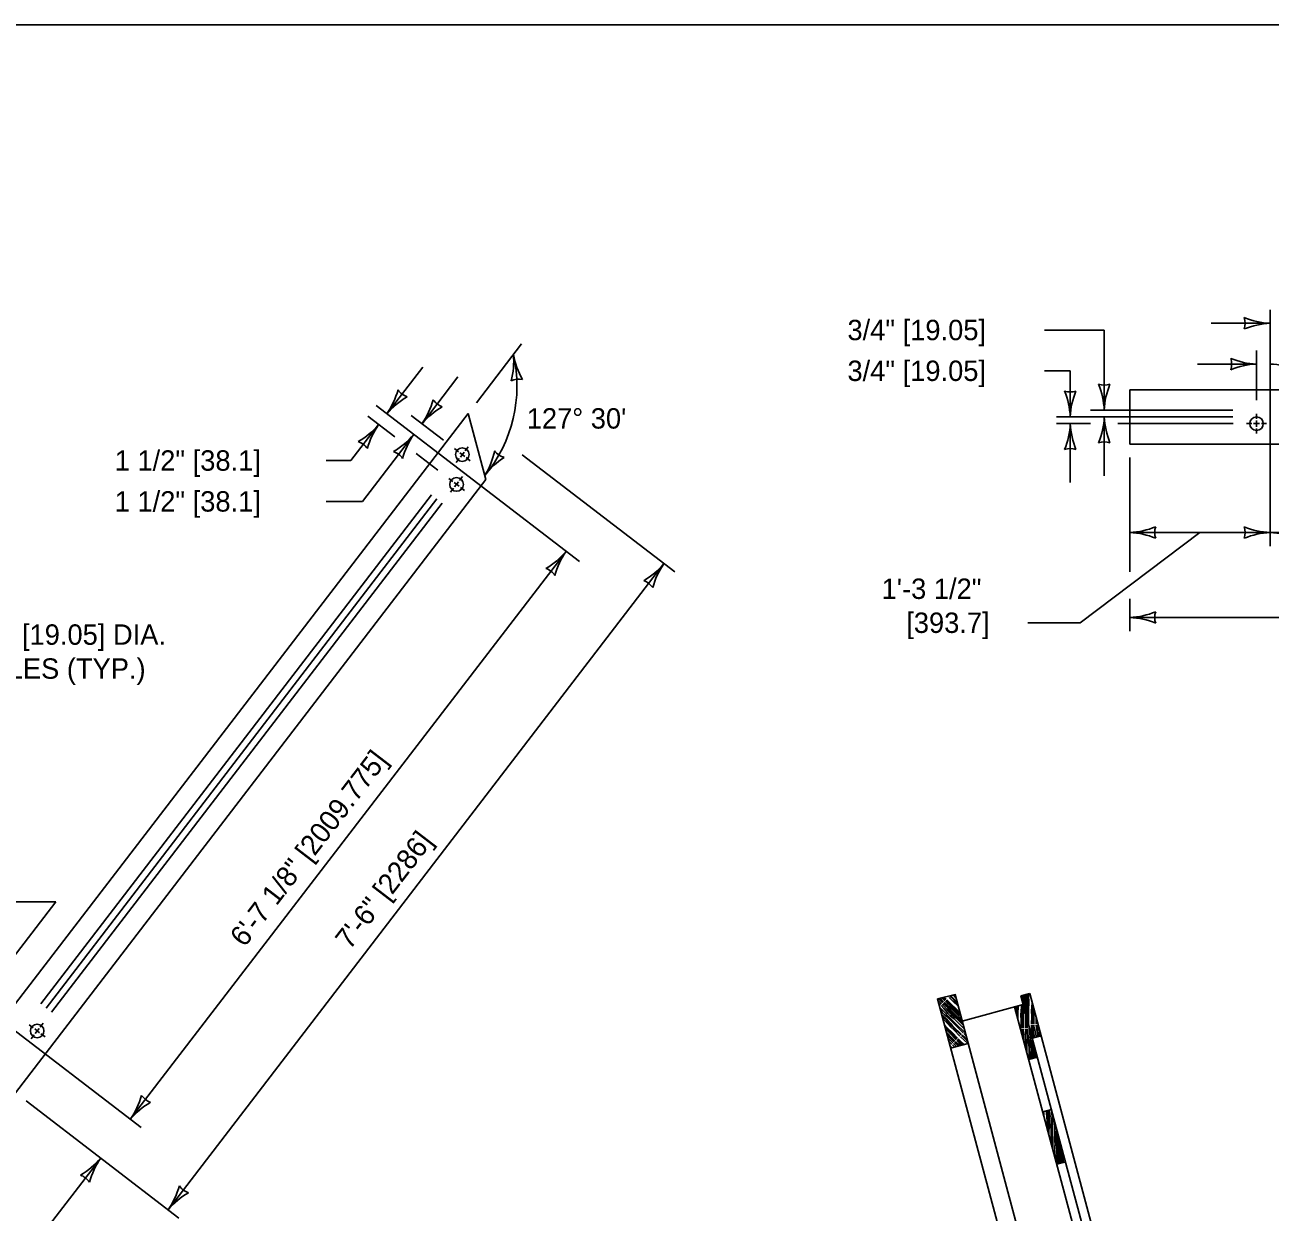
# Model space of a CAD drawing. Extents: x 49991 to 79985, y 47703 to 60542.
# Drawn here: x 50009.323 to 50012.986, y 49995.507 to 49998.999 of the extents above; entities that cross this region are included whole.
import ezdxf

# ---------------------------------------------------------------- set-up
doc = ezdxf.new("R2010")
doc.units = 0
for name, color, linetype in [('Level 1', 7, 'Continuous'), ('Level 2', 7, 'Continuous'), ('Level 3', 7, 'Continuous'), ('Level 4', 7, 'Continuous'), ('Level 5', 7, 'Continuous')]:
    doc.layers.add(name, color=color, linetype=linetype)

msp = doc.modelspace()

# ---------------------------------------------------------------- linework, layer by layer
at = {"layer": 'Level 1'}
for p, q in [((50015.1288, 49997.926), (50012.5733, 49997.926)), ((50012.5733, 49997.926), (50012.5733, 49997.7663)), ((50009.1686, 49995.9554), (50010.6271, 49997.8561)), ((50010.6794, 49997.6615), (50010.6271, 49997.8561)), ((50012.5733, 49997.7663), (50015.1288, 49997.7663)), ((50009.2955, 49995.858), (50010.6794, 49997.6615)), ((50012.0075, 49996.134), (50012.0592, 49996.1469)), ((50012.2427, 49995.2562), (50012.0075, 49996.134)), ((50012.0075, 49996.134), (50012.0076, 49996.1336)), ((50012.7492, 49993.5717), (50012.0592, 49996.1469)), ((50012.0801, 49996.069), (50012.26, 49996.1172)), ((50012.2531, 49996.1429), (50012.2788, 49996.1497)), ((50012.6896, 49994.5138), (50012.2531, 49996.1429)), ((50012.7172, 49994.5138), (50012.2788, 49996.1497)), ((50012.6693, 49994.4868), (50012.2343, 49996.1103)), ((50012.2865, 49996.0181), (50012.3122, 49996.025)), ((50012.0463, 49995.9892), (50012.0978, 49996.0029)), ((50012.2756, 49995.956), (50012.3013, 49995.9629)), ((50012.317, 49995.8017), (50012.3427, 49995.8086)), ((50012.3583, 49995.6475), (50012.384, 49995.6543))]:
    msp.add_line(p, q, dxfattribs=at)
msp.add_lwpolyline([(49999.3835, 49998.9992), (50016.7501, 49998.9992), (50016.7501, 49987.7988), (49999.3835, 49987.7988)], close=True, dxfattribs=at)
for points in [[(50012.0084, 49996.1308), (50012.0194, 49996.1194)], [(50012.0102, 49996.1347), (50012.0226, 49996.1225)], [(50012.0108, 49996.1215), (50012.0163, 49996.1162)], [(50012.0126, 49996.1353), (50012.0241, 49996.1241)], [(50012.0153, 49996.136), (50012.0257, 49996.1256)], [(50012.0207, 49996.1373), (50012.0289, 49996.1288)], [(50012.0213, 49996.1175), (50012.0345, 49996.1052), (50012.0444, 49996.092), (50012.0522, 49996.0841), (50012.0567, 49996.0814), (50012.0629, 49996.0769), (50012.073, 49996.0665), (50012.0837, 49996.0554)], [(50012.0236, 49996.138), (50012.0304, 49996.1304)], [(50012.0245, 49996.1207), (50012.0377, 49996.1084), (50012.05, 49996.0924), (50012.0646, 49996.0796), (50012.0789, 49996.0659), (50012.0816, 49996.0633)], [(50012.026, 49996.1222), (50012.0392, 49996.1099), (50012.0542, 49996.0933), (50012.0661, 49996.0811), (50012.0804, 49996.0674), (50012.0805, 49996.0674)], [(50012.0276, 49996.1237), (50012.0362, 49996.1161), (50012.045, 49996.1083), (50012.0611, 49996.0921), (50012.0779, 49996.0741), (50012.079, 49996.0729)], [(50012.0277, 49996.1391), (50012.0334, 49996.1333)], [(50012.0307, 49996.1269), (50012.0616, 49996.0972), (50012.0766, 49996.0819)], [(50012.0323, 49996.1285), (50012.0394, 49996.1229), (50012.0489, 49996.1143), (50012.075, 49996.0878)], [(50012.0353, 49996.1314), (50012.0482, 49996.1189), (50012.0629, 49996.1045), (50012.0735, 49996.0934)], [(50012.0381, 49996.1416), (50012.0398, 49996.1398)], [(50012.0417, 49996.1379), (50012.0523, 49996.1273), (50012.0683, 49996.1129)], [(50012.0666, 49996.1192), (50012.0647, 49996.1208), (50012.0554, 49996.1311), (50012.0432, 49996.1427)], [(50012.0652, 49996.1243), (50012.0639, 49996.1254), (50012.055, 49996.1353), (50012.0465, 49996.1427)], [(50012.0621, 49996.1361), (50012.057, 49996.1426), (50012.0536, 49996.1455)], [(50012.0596, 49996.1455), (50012.0583, 49996.1467)], [(50012.2551, 49996.1353), (50012.2563, 49996.1436), (50012.2563, 49996.1438)], [(50012.2576, 49996.0478), (50012.257, 49996.0746), (50012.2568, 49996.0937), (50012.2584, 49996.1072), (50012.2576, 49996.1166)], [(50012.2583, 49996.1236), (50012.2608, 49996.1436), (50012.2608, 49996.1449)], [(50012.2617, 49996.1107), (50012.2618, 49996.1213), (50012.263, 49996.1436), (50012.2629, 49996.1455)], [(50012.2652, 49996.0975), (50012.2659, 49996.1155), (50012.2659, 49996.1383), (50012.2654, 49996.1462)], [(50012.2694, 49996.0819), (50012.2695, 49996.0877), (50012.2698, 49996.1188), (50012.2692, 49996.1472)], [(50012.272, 49996.0722), (50012.2725, 49996.0807), (50012.2729, 49996.1398), (50012.2725, 49996.1481)], [(50012.2754, 49996.0596), (50012.2757, 49996.0824), (50012.2754, 49996.1025), (50012.2759, 49996.123), (50012.2757, 49996.1436), (50012.2756, 49996.1489)], [(50012.2845, 49996.0594), (50012.2851, 49996.0829), (50012.2845, 49996.0982), (50012.2857, 49996.1225), (50012.2856, 49996.1243)], [(50012.0897, 49996.0336), (50012.0588, 49996.0633), (50012.0377, 49996.0847), (50012.0304, 49996.0933), (50012.0142, 49996.1089)], [(50012.0161, 49996.1018), (50012.0162, 49996.1018), (50012.0228, 49996.0932), (50012.0271, 49996.0886), (50012.0361, 49996.0812), (50012.0503, 49996.0661), (50012.0827, 49996.0343)], [(50012.0181, 49996.1143), (50012.0266, 49996.1055), (50012.0336, 49996.0975), (50012.0381, 49996.0911), (50012.0447, 49996.0842), (50012.0497, 49996.0804), (50012.0562, 49996.0752), (50012.0638, 49996.0682), (50012.0862, 49996.0462)], [(50012.078, 49996.0296), (50012.0518, 49996.0552), (50012.049, 49996.0587), (50012.0482, 49996.0611), (50012.037, 49996.0729), (50012.0231, 49996.0846), (50012.0198, 49996.0883)], [(50012.0212, 49996.0829), (50012.0238, 49996.08), (50012.0349, 49996.0705), (50012.0434, 49996.0598), (50012.057, 49996.0465), (50012.0764, 49996.028)], [(50012.2344, 49996.1099), (50012.2344, 49996.1103)], [(50012.2382, 49996.0958), (50012.2383, 49996.1072), (50012.2382, 49996.1114)], [(50012.2382, 49996.0957), (50012.2382, 49996.0958)], [(50012.2411, 49996.0848), (50012.2414, 49996.1122)], [(50012.2411, 49996.0848), (50012.2411, 49996.0848)], [(50012.2442, 49996.0735), (50012.244, 49996.0909), (50012.2444, 49996.1115), (50012.2444, 49996.113)], [(50012.253, 49996.0478), (50012.2536, 49996.0714), (50012.253, 49996.0866), (50012.2543, 49996.111), (50012.254, 49996.1156)], [(50012.2599, 49996.0478), (50012.2595, 49996.0844), (50012.26, 49996.0889), (50012.2611, 49996.0912), (50012.2616, 49996.1074), (50012.261, 49996.1132)], [(50012.2661, 49996.0943), (50012.2661, 49996.0943)], [(50012.2665, 49996.0478), (50012.2661, 49996.0932), (50012.2661, 49996.0943)], [(50012.2891, 49996.0594), (50012.2885, 49996.0862), (50012.2882, 49996.1052), (50012.289, 49996.1117)], [(50012.2913, 49996.0594), (50012.291, 49996.096), (50012.2914, 49996.1005), (50012.2918, 49996.1012)], [(50012.0231, 49996.076), (50012.0293, 49996.0703), (50012.0457, 49996.0522), (50012.0569, 49996.0418), (50012.0731, 49996.0247)], [(50012.028, 49996.0574), (50012.0362, 49996.0488), (50012.0506, 49996.0348), (50012.0667, 49996.0183)], [(50012.0638, 49996.0154), (50012.0496, 49996.0313), (50012.0296, 49996.0516)], [(50012.0312, 49996.0457), (50012.0425, 49996.0342), (50012.0622, 49996.0138)], [(50012.253, 49996.0404), (50012.253, 49996.0451)], [(50012.2576, 49996.0235), (50012.2579, 49996.0306), (50012.2576, 49996.0451)], [(50012.2608, 49996.0116), (50012.26, 49996.0206), (50012.2606, 49996.0339), (50012.2599, 49996.0451)], [(50012.2662, 49995.9913), (50012.2668, 49996.0091), (50012.2656, 49996.0206), (50012.2658, 49996.0269), (50012.2672, 49996.0377), (50012.2665, 49996.0451)], [(50012.2703, 49995.9761), (50012.2702, 49995.9803), (50012.2704, 49996.0103), (50012.2713, 49996.0216), (50012.2709, 49996.0451)], [(50012.2709, 49996.0478), (50012.2703, 49996.0786)], [(50012.2774, 49995.9565), (50012.2772, 49995.9803), (50012.2768, 49995.9905), (50012.2759, 49995.9988), (50012.2749, 49996.0051), (50012.2752, 49996.0146), (50012.2765, 49996.0224), (50012.2772, 49996.0329), (50012.2776, 49996.0476)], [(50012.2775, 49996.0478), (50012.2774, 49996.0519)], [(50012.2855, 49996.0217), (50012.2845, 49996.0417), (50012.2845, 49996.0567)], [(50012.2895, 49996.0189), (50012.2887, 49996.0284), (50012.2894, 49996.0422), (50012.2891, 49996.0567)], [(50012.2925, 49996.0197), (50012.2914, 49996.0322), (50012.2921, 49996.0455), (50012.2913, 49996.0567)], [(50012.2982, 49996.0212), (50012.2971, 49996.0322), (50012.2973, 49996.0385), (50012.2987, 49996.0492), (50012.298, 49996.0567)], [(50012.298, 49996.0594), (50012.2978, 49996.0789)], [(50012.3019, 49996.0222), (50012.3028, 49996.0332), (50012.3024, 49996.0567)], [(50012.3024, 49996.0594), (50012.3023, 49996.0619)], [(50012.3023, 49996.0619), (50012.3023, 49996.0619)], [(50012.0335, 49996.0371), (50012.037, 49996.0333), (50012.0498, 49996.0198), (50012.059, 49996.0106)], [(50012.0575, 49996.0091), (50012.0395, 49996.0266), (50012.0352, 49996.0308)], [(50012.0352, 49996.0308), (50012.0395, 49996.0266), (50012.0575, 49996.0091)], [(50012.0362, 49996.0268), (50012.0381, 49996.0251), (50012.0559, 49996.0075)], [(50012.0527, 49996.0044), (50012.0382, 49996.0193)], [(50012.0408, 49996.0099), (50012.0408, 49996.0099)], [(50012.0408, 49996.0099), (50012.0496, 49996.0012)], [(50012.0593, 49996.0072), (50012.0715, 49995.9959)], [(50012.0609, 49996.0087), (50012.0695, 49996.0011), (50012.0745, 49995.9967)], [(50012.0641, 49996.0119), (50012.0786, 49995.9978)], [(50012.0826, 49995.9989), (50012.0822, 49995.9993), (50012.0727, 49996.0079), (50012.0657, 49996.0135)], [(50012.0686, 49996.0164), (50012.0815, 49996.0039), (50012.0858, 49995.9997)], [(50012.075, 49996.0229), (50012.0856, 49996.0123), (50012.0964, 49996.0026)], [(50012.0783, 49996.0261), (50012.0887, 49996.0161), (50012.0966, 49996.0074)], [(50012.0951, 49996.0128), (50012.0883, 49996.0203), (50012.0798, 49996.0277)], [(50012.0846, 49996.0324), (50012.0903, 49996.0276), (50012.0916, 49996.026)], [(50012.2576, 49996.0235), (50012.2576, 49996.0235)], [(50012.2822, 49995.9578), (50012.2824, 49995.9725), (50012.2827, 49995.987), (50012.2815, 49995.9947), (50012.2802, 49995.9997), (50012.2802, 49996.0108), (50012.2826, 49996.0271), (50012.2824, 49996.0334)], [(50012.2824, 49996.0334), (50012.2824, 49996.0334)], [(50012.2863, 49995.9589), (50012.2862, 49995.968), (50012.2858, 49995.9878), (50012.2846, 49996.0071), (50012.2862, 49996.0194)], [(50012.2884, 49995.9595), (50012.2884, 49995.968), (50012.2879, 49995.9878), (50012.2881, 49996.0048), (50012.2884, 49996.0109)], [(50012.3066, 49996.0235), (50012.3066, 49996.0262), (50012.308, 49996.034), (50012.3083, 49996.0394)], [(50012.3083, 49996.0394), (50012.3083, 49996.0394)], [(50012.312, 49996.025), (50012.3121, 49996.0254)], [(50012.0512, 49995.9905), (50012.0442, 49995.9972)], [(50012.0515, 49995.9993), (50012.0582, 49995.9923)], [(50012.0639, 49995.9939), (50012.0546, 49996.0025)], [(50012.0578, 49996.0057), (50012.0691, 49995.9952)], [(50012.2909, 49995.9601), (50012.2913, 49995.9745), (50012.2921, 49995.9971)], [(50012.2921, 49995.9971), (50012.2921, 49995.9971)], [(50012.2956, 49995.9614), (50012.2958, 49995.9712), (50012.2959, 49995.9829)], [(50012.2959, 49995.9829), (50012.2959, 49995.983)], [(50012.2987, 49995.9622), (50012.2988, 49995.9642), (50012.2988, 49995.972)], [(50012.3199, 49995.7906), (50012.3199, 49995.7956), (50012.3198, 49995.8025)], [(50012.329, 49995.7566), (50012.3299, 49995.7745), (50012.3287, 49995.7986), (50012.3287, 49995.8049)], [(50012.3326, 49995.7433), (50012.3324, 49995.7572), (50012.3341, 49995.7707), (50012.3329, 49995.7853), (50012.3336, 49995.7991), (50012.3334, 49995.8062)], [(50012.3353, 49995.7332), (50012.3352, 49995.7479), (50012.3356, 49995.7524), (50012.3368, 49995.7547), (50012.3372, 49995.771), (50012.3356, 49995.789), (50012.3363, 49995.8023), (50012.336, 49995.8069)], [(50012.3422, 49995.7075), (50012.3418, 49995.7567), (50012.3425, 49995.7775), (50012.3413, 49995.789), (50012.3415, 49995.7953), (50012.3429, 49995.8061), (50012.3427, 49995.8082)], [(50012.3427, 49995.8082), (50012.3427, 49995.8082)], [(50012.3466, 49995.7113), (50012.3459, 49995.7487), (50012.3461, 49995.7788), (50012.347, 49995.79), (50012.347, 49995.7923)], [(50012.3532, 49995.7113), (50012.3529, 49995.7487), (50012.3524, 49995.759), (50012.3515, 49995.7672), (50012.3506, 49995.7735), (50012.3507, 49995.7782)], [(50012.3577, 49995.7113), (50012.3581, 49995.7409), (50012.3583, 49995.7501)], [(50012.3326, 49995.7432), (50012.3326, 49995.7433)], [(50012.3622, 49995.7113), (50012.3619, 49995.7364), (50012.3619, 49995.7365)], [(50012.3643, 49995.7113), (50012.3641, 49995.7282)], [(50012.3665, 49995.7113), (50012.3665, 49995.7194)], [(50012.3423, 49995.707), (50012.3422, 49995.7087)], [(50012.3469, 49995.69), (50012.3465, 49995.7118)], [(50012.3508, 49995.6755), (50012.3508, 49995.6781), (50012.3522, 49995.6859), (50012.3529, 49995.6964), (50012.3533, 49995.7121)], [(50012.3583, 49995.6475), (50012.3583, 49995.6506), (50012.3571, 49995.6582), (50012.3559, 49995.6633), (50012.3559, 49995.6743), (50012.3583, 49995.6907), (50012.3576, 49995.7117)], [(50012.3615, 49995.6483), (50012.3615, 49995.6513), (50012.3602, 49995.6707), (50012.3628, 49995.6907), (50012.3621, 49995.7119)], [(50012.3636, 49995.6489), (50012.3636, 49995.6513), (50012.3638, 49995.6684), (50012.3649, 49995.6907), (50012.3642, 49995.7116)], [(50012.3674, 49995.6499), (50012.3679, 49995.6626), (50012.3679, 49995.6854), (50012.3672, 49995.6972), (50012.3663, 49995.7115)], [(50012.3716, 49995.651), (50012.3717, 49995.6659), (50012.3711, 49995.7023)], [(50012.3711, 49995.7023), (50012.3711, 49995.7023)], [(50012.3746, 49995.6518), (50012.3749, 49995.6869), (50012.3748, 49995.6883)], [(50012.3748, 49995.6883), (50012.3748, 49995.6883)], [(50012.3775, 49995.6526), (50012.3779, 49995.6701), (50012.3778, 49995.6772)], [(50012.3778, 49995.6772), (50012.3778, 49995.6773)]]:
    msp.add_lwpolyline(points, dxfattribs=at)
for centre in [(50012.946, 49997.8262), (50010.6098, 49997.7351), (50010.593, 49997.6475), (50009.3594, 49996.0398)]:
    msp.add_circle(centre, 0.02, dxfattribs=at)
at = {"layer": 'Level 3'}
for p, q in [((50012.9859, 49998.1615), (50012.9859, 49997.466)), ((50012.4981, 49998.1017), (50012.3227, 49998.1017)), ((50012.4981, 49998.1017), (50012.4981, 49997.8661)), ((50012.8125, 49998.1215), (50012.9859, 49998.1215)), ((50010.6514, 49997.8878), (50010.7845, 49998.061)), ((50012.946, 49998.0415), (50012.946, 49997.8955)), ((50010.3878, 49997.8552), (50010.4934, 49997.9927)), ((50012.7726, 49998.0015), (50012.946, 49998.0015)), ((50010.4914, 49997.8259), (50010.597, 49997.9635)), ((50012.3981, 49997.9817), (50012.3227, 49997.9817)), ((50012.3981, 49997.9817), (50012.3981, 49997.8462)), ((50010.9543, 49997.4205), (50010.3562, 49997.8795)), ((50010.3319, 49997.848), (50010.4111, 49997.7871)), ((50010.5549, 49997.7772), (50010.4596, 49997.8503)), ((50012.3581, 49997.8462), (50012.876, 49997.8462)), ((50012.4581, 49997.8661), (50012.876, 49997.8661)), ((50012.4981, 49997.8462), (50012.4981, 49997.6728)), ((50010.2825, 49997.7178), (50010.3636, 49997.8236)), ((50012.3581, 49997.8262), (50012.4581, 49997.8262)), ((50012.3981, 49997.8262), (50012.3981, 49997.6528)), ((50012.5381, 49997.8262), (50012.8768, 49997.8262)), ((50010.3161, 49997.5975), (50010.4671, 49997.7943)), ((50010.5381, 49997.6896), (50010.4746, 49997.7383)), ((50010.7857, 49997.7343), (50011.2348, 49997.39)), ((50010.2825, 49997.7178), (50010.2095, 49997.7178)), ((50012.5733, 49997.7263), (50012.5733, 49997.3906)), ((50009.3698, 49996.1191), (50010.5191, 49997.6169)), ((50009.3857, 49996.1069), (50010.535, 49997.6047)), ((50009.4016, 49996.0948), (50010.5509, 49997.5925)), ((50010.3161, 49997.5975), (50010.2095, 49997.5975)), ((50012.5733, 49997.506), (50012.9859, 49997.506)), ((50012.9859, 49997.506), (50014.7162, 49997.506)), ((50009.6334, 49995.7798), (50010.9152, 49997.4505)), ((50009.7446, 49995.5137), (50011.203, 49997.4144)), ((50012.5733, 49997.3106), (50012.5733, 49997.216)), ((50012.5733, 49997.256), (50015.1288, 49997.256)), ((50009.4139, 49996.4192), (50009.1228, 49996.4192)), ((50009.2106, 49996.1543), (50009.4139, 49996.4192)), ((50009.0751, 49996.2081), (50009.6651, 49995.7554)), ((50009.3273, 49995.8337), (50009.7764, 49995.4893)), ((50009.3697, 49995.4353), (50009.5463, 49995.6657))]:
    msp.add_line(p, q, dxfattribs=at)
msp.add_lwpolyline([(50012.7796, 49997.506), (50012.4272, 49997.2406), (50012.2737, 49997.2406)], dxfattribs=at)
for centre, radius, start, end in [((50012.9951, 49998.3436), 0.2223, 247.456, 267.6395), ((50012.8577, 49998.1215), 0.0548, 342.1388, 17.8612), ((50012.9974, 49997.8888), 0.233, 92.8273, 112.0772), ((50010.3577, 49997.9367), 0.4129, 320.4245, 12.9573), ((50010.5388, 49998.0082), 0.2223, 345.2736, 5.4571), ((50010.9891, 49998.0724), 0.233, 190.6449, 209.8947), ((50012.9552, 49998.2236), 0.2223, 247.456, 267.6395), ((50012.8178, 49998.0015), 0.0548, 342.1388, 17.8612), ((50012.9575, 49997.7688), 0.233, 92.8273, 112.0772), ((50012.9767, 49997.7794), 0.2223, 67.456, 87.6395), ((50010.7775, 49997.9023), 0.0548, 79.9564, 115.6788), ((50010.1963, 49997.9878), 0.233, 325.2889, 344.5388), ((50010.466, 49997.9568), 0.0548, 214.6004, 250.3228), ((50012.3981, 49997.9744), 0.0548, 252.1388, 287.8612), ((50012.1654, 49997.8347), 0.233, 2.8273, 22.0772), ((50012.6202, 49997.837), 0.2223, 157.456, 177.6395), ((50012.4981, 49997.9943), 0.0548, 252.1388, 287.8612), ((50012.2654, 49997.8546), 0.233, 2.8273, 22.0772), ((50012.7202, 49997.8569), 0.2223, 157.456, 177.6395), ((50010.5584, 49997.7125), 0.2223, 119.9176, 140.1011), ((50010.2998, 49997.9586), 0.233, 325.2971, 344.5469), ((50010.662, 49997.6833), 0.2223, 119.9258, 140.1093), ((50010.5695, 49997.9276), 0.0548, 214.6086, 250.3309), ((50012.276, 49997.8554), 0.2223, 337.456, 357.6395), ((50012.7308, 49997.8577), 0.233, 182.8273, 202.0772), ((50010.1929, 49997.966), 0.2223, 299.9844, 320.1679), ((50010.5553, 49997.6911), 0.233, 145.3557, 164.6055), ((50012.176, 49997.8354), 0.2223, 337.456, 357.6395), ((50012.6308, 49997.8377), 0.233, 182.8273, 202.0772), ((50010.2856, 49997.7218), 0.0548, 34.6672, 70.3896), ((50010.2965, 49997.9368), 0.2223, 299.9664, 320.1499), ((50010.6588, 49997.6618), 0.233, 145.3377, 164.5875), ((50012.4981, 49997.718), 0.0548, 72.1388, 107.8612), ((50010.3891, 49997.6926), 0.0548, 34.6492, 70.3715), ((50010.4775, 49997.7958), 0.233, 328.3998, 347.6496), ((50010.7484, 49997.7794), 0.0548, 217.7113, 253.4336), ((50012.3981, 49997.698), 0.0548, 72.1388, 107.8612), ((50010.854, 49997.5406), 0.2223, 123.0285, 143.212), ((50012.5618, 49997.7387), 0.233, 272.8273, 292.0772), ((50012.7015, 49997.506), 0.0548, 162.1388, 197.8612), ((50012.9951, 49997.7281), 0.2223, 247.456, 267.6395), ((50012.8577, 49997.506), 0.0548, 342.1388, 17.8612), ((50012.5641, 49997.2839), 0.2223, 67.456, 87.6395), ((50012.9974, 49997.2733), 0.233, 92.8273, 112.0772), ((50012.9767, 49997.2839), 0.2223, 67.456, 87.6395), ((50010.7446, 49997.5929), 0.2223, 299.9577, 320.1413), ((50011.1069, 49997.3179), 0.233, 145.329, 164.5789), ((50010.8372, 49997.3487), 0.0548, 34.6405, 70.3629), ((50011.0324, 49997.5568), 0.2223, 299.9571, 320.1406), ((50011.3946, 49997.2818), 0.233, 145.3284, 164.5783), ((50011.125, 49997.3126), 0.0548, 34.6399, 70.3623), ((50012.5618, 49997.4887), 0.233, 272.8273, 292.0772), ((50012.5641, 49997.0339), 0.2223, 67.456, 87.6395), ((50012.7015, 49997.256), 0.0548, 162.1388, 197.8612), ((50009.4418, 49995.9123), 0.233, 325.3302, 344.58), ((50009.8041, 49995.6373), 0.2223, 119.9589, 140.1424), ((50009.7114, 49995.8815), 0.0548, 214.6417, 250.3641), ((50009.3755, 49995.8081), 0.2223, 299.9908, 320.1743), ((50009.738, 49995.5333), 0.233, 145.3621, 164.6119), ((50009.4683, 49995.564), 0.0548, 34.6736, 70.396), ((50009.553, 49995.6462), 0.233, 325.3284, 344.5783), ((50009.8227, 49995.6154), 0.0548, 214.6399, 250.3623), ((50009.9153, 49995.3712), 0.2223, 119.9571, 140.1406)]:
    msp.add_arc(centre, radius, start, end, dxfattribs=at)
at = {"layer": 'Level 4'}
msp.add_line((50012.0075, 49996.134), (50012.0075, 49996.134), dxfattribs=at)
at = {"layer": 'Level 5'}
for p, q in [((50012.946, 49997.8555), (50012.946, 49997.8405)), ((50012.9168, 49997.8262), (50012.9318, 49997.8262)), ((50012.9368, 49997.8262), (50012.9552, 49997.8262)), ((50012.946, 49997.8355), (50012.946, 49997.817)), ((50012.946, 49997.8119), (50012.946, 49997.7969)), ((50012.9603, 49997.8262), (50012.9753, 49997.8262)), ((50010.5866, 49997.7529), (50010.5985, 49997.7437)), ((50010.6025, 49997.7407), (50010.6171, 49997.7294)), ((50010.6042, 49997.7277), (50010.6154, 49997.7424)), ((50010.6185, 49997.7464), (50010.6276, 49997.7583)), ((50010.592, 49997.7118), (50010.6011, 49997.7237)), ((50010.6211, 49997.7264), (50010.633, 49997.7172)), ((50010.5698, 49997.6653), (50010.5817, 49997.6562)), ((50010.5874, 49997.6401), (50010.5987, 49997.6548)), ((50010.6017, 49997.6588), (50010.6108, 49997.6707)), ((50010.5752, 49997.6243), (50010.5844, 49997.6362)), ((50010.5857, 49997.6531), (50010.6004, 49997.6419)), ((50010.6043, 49997.6388), (50010.6162, 49997.6297)), ((50009.3362, 49996.0576), (50009.3481, 49996.0485)), ((50009.3521, 49996.0455), (50009.3667, 49996.0342)), ((50009.3538, 49996.0325), (50009.365, 49996.0472)), ((50009.3681, 49996.0511), (50009.3772, 49996.063)), ((50009.3416, 49996.0166), (50009.3507, 49996.0285)), ((50009.3707, 49996.0312), (50009.3826, 49996.022))]:
    msp.add_line(p, q, dxfattribs=at)

# ---------------------------------------------------------------- texts
at = {"layer": 'Level 2'}
for s, p in [('3/4" [19.05]', (50011.7427, 49998.0717)), ('3/4" [19.05]', (50011.7427, 49997.9517)), ("127° 30'", (50010.7995, 49997.8117)), ('1 1/2" [38.1]', (50009.5875, 49997.6878)), ('1 1/2" [38.1]', (50009.5875, 49997.5675)), ('1\'-3 1/2"', (50011.8433, 49997.3106)), ('[393.7]', (50011.9157, 49997.2106)), ('3/4" [19.05] DIA.', (50009.1524, 49997.1758)), ('HOLES (TYP.)', (50009.1524, 49997.0758))]:
    msp.add_text(s, height=0.06, dxfattribs=at).set_placement(p)
for s, p in [('6\'-7 1/8" [2009.775]', (50009.9696, 49996.2837)), ('7\'-6" [2286]', (50010.2792, 49996.2761))]:
    msp.add_text(s, height=0.06, rotation=52.5024, dxfattribs=at).set_placement(p)

doc.saveas('drawing.dxf')
